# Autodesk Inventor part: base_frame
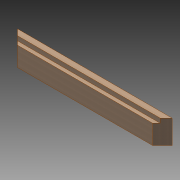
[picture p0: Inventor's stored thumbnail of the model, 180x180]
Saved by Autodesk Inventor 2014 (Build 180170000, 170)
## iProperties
Created: 2014-05
Part Number: base_frame
Material: Maple
Document SubType Name: Modeling
Designer: t_emanb
Density: 1 g/cm^3
Appearance: Maple - Solid Natural Medium Gloss
Author: t_emanb
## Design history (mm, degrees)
sketch "Sketch1"
  geometry: L1 (0, 0)-(101.6, 0); L2 (101.6, 0)-(101.6, 41.275); L3 (101.6, 41.275)-(0, 41.275); L4 (0, 41.275)-(0, 0)
  constraints: 8 end point, 2 parallel, 1 horizontal, 1 perpendicular
  dimensions: "d0" = 101.6 distance of L2.end L3.end; "d1" = 41.275 distance of L1.end L2.end
extrude "Extrusion1" new body sketch "Sketch1" distance "d2" = 660.4; taper "d3" = 0 deg
sketch "Sketch2"
  geometry: L1 (0, 0)-(0, 101.6) reference; L2 (0, 101.6)-(-41.275, 101.6) reference; L3 (-41.275, 101.6)-(-41.275, 0) reference; L4 (-41.275, 0)-(0, 0) reference; L5 (-25.4, 101.6)-(-25.4, 82.55); L6 (-25.4, 82.55)-(-41.275, 82.55)
  constraints: 4 end point, 2 perpendicular, 2 point on line
  dimensions: "d4" = 19.05 distance of L5.start L5.end; "d5" = 25.4 distance between parallel lines of L1 L5
extrude "Extrusion2" cut sketch "Sketch2" stored distance "d6" = 660.4; taper "d7" = 0 deg
sketch "Sketch3"
  geometry: L1 (0, 41.275)-(0, 0) reference; L2 (660.4, 41.275)-(660.4, 0) reference; L3 (0, 41.275)-(660.4, 41.275) reference; L4 (0, 0)-(41.275, 41.275); L5 (660.4, 0)-(619.125, 41.275)
  constraints: 4 end point, 2 point on line
  dimensions: "d8" = 45 deg angle of L1 L4; "d9" = 45 deg angle of L2 L5
extrude "Extrusion3" cut sketch "Sketch3" stored distance "d10" = 660.4; taper "d11" = 0 deg
body "Solid1"
